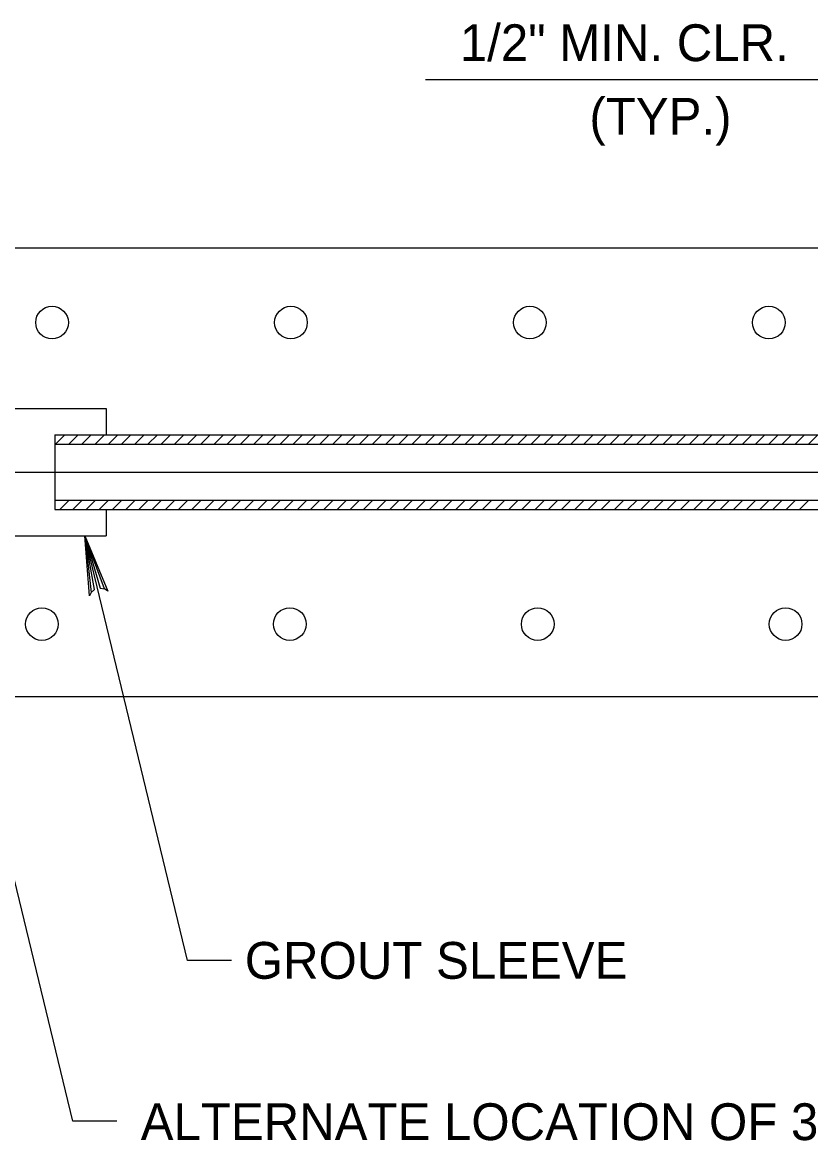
# Model space of a CAD drawing. Extents: x 641328 to 643024, y 298283 to 300065.
# Drawn here: x 642334.5 to 642398.8, y 299308 to 299399.2 of the extents above; entities that cross this region are included whole.
import ezdxf

# ---------------------------------------------------------------- set-up
doc = ezdxf.new("R2010")
doc.units = 0
doc.layers.add('2', color=7, linetype='Continuous')
doc.layers.add('Default', color=7, linetype='Continuous')

msp = doc.modelspace()

# ---------------------------------------------------------------- linework, layer by layer
at = {"layer": '2'}
for p, q in [((642367.417, 299394.518), (642420.173, 299394.518)), ((642292.048, 299380.803), (642421.968, 299380.803)), ((642331.817, 299367.696), (642341.364, 299367.696)), ((642341.364, 299367.696), (642341.364, 299365.563)), ((642337.162, 299365.563), (642423.111, 299365.563)), ((642337.162, 299365.563), (642337.162, 299359.467)), ((642337.229, 299364.801), (642337.991, 299365.563)), ((642338.307, 299364.801), (642339.069, 299365.563)), ((642339.385, 299364.801), (642340.147, 299365.563)), ((642340.462, 299364.801), (642341.224, 299365.563)), ((642341.54, 299364.801), (642342.302, 299365.563)), ((642342.618, 299364.801), (642343.38, 299365.563)), ((642343.695, 299364.801), (642344.457, 299365.563)), ((642344.773, 299364.801), (642345.535, 299365.563)), ((642345.85, 299364.801), (642346.612, 299365.563)), ((642346.928, 299364.801), (642347.69, 299365.563)), ((642348.006, 299364.801), (642348.768, 299365.563)), ((642349.083, 299364.801), (642349.845, 299365.563)), ((642350.161, 299364.801), (642350.923, 299365.563)), ((642351.239, 299364.801), (642352.001, 299365.563)), ((642352.316, 299364.801), (642353.078, 299365.563)), ((642353.394, 299364.801), (642354.156, 299365.563)), ((642354.472, 299364.801), (642355.234, 299365.563)), ((642355.549, 299364.801), (642356.311, 299365.563)), ((642356.627, 299364.801), (642357.389, 299365.563)), ((642357.704, 299364.801), (642358.466, 299365.563)), ((642358.782, 299364.801), (642359.544, 299365.563)), ((642359.86, 299364.801), (642360.622, 299365.563)), ((642360.937, 299364.801), (642361.699, 299365.563)), ((642362.015, 299364.801), (642362.777, 299365.563)), ((642363.093, 299364.801), (642363.855, 299365.563)), ((642364.17, 299364.801), (642364.932, 299365.563)), ((642365.248, 299364.801), (642366.01, 299365.563)), ((642366.325, 299364.801), (642367.087, 299365.563)), ((642367.403, 299364.801), (642368.165, 299365.563)), ((642368.481, 299364.801), (642369.243, 299365.563)), ((642369.558, 299364.801), (642370.32, 299365.563)), ((642370.636, 299364.801), (642371.398, 299365.563)), ((642371.714, 299364.801), (642372.476, 299365.563)), ((642372.791, 299364.801), (642373.553, 299365.563)), ((642373.869, 299364.801), (642374.631, 299365.563)), ((642374.947, 299364.801), (642375.709, 299365.563)), ((642376.024, 299364.801), (642376.786, 299365.563)), ((642377.102, 299364.801), (642377.864, 299365.563)), ((642378.179, 299364.801), (642378.941, 299365.563)), ((642379.257, 299364.801), (642380.019, 299365.563)), ((642380.335, 299364.801), (642381.097, 299365.563)), ((642381.412, 299364.801), (642382.174, 299365.563)), ((642382.49, 299364.801), (642383.252, 299365.563)), ((642383.568, 299364.801), (642384.33, 299365.563)), ((642384.645, 299364.801), (642385.407, 299365.563)), ((642385.723, 299364.801), (642386.485, 299365.563)), ((642386.801, 299364.801), (642387.563, 299365.563)), ((642387.878, 299364.801), (642388.64, 299365.563)), ((642388.956, 299364.801), (642389.718, 299365.563)), ((642390.033, 299364.801), (642390.795, 299365.563)), ((642391.111, 299364.801), (642391.873, 299365.563)), ((642392.189, 299364.801), (642392.951, 299365.563)), ((642393.266, 299364.801), (642394.028, 299365.563)), ((642394.344, 299364.801), (642395.106, 299365.563)), ((642395.422, 299364.801), (642396.184, 299365.563)), ((642396.499, 299364.801), (642397.261, 299365.563)), ((642397.577, 299364.801), (642398.339, 299365.563)), ((642398.654, 299364.801), (642399.416, 299365.563)), ((642337.162, 299364.801), (642423.111, 299364.801)), ((642229.139, 299362.515), (642534.829, 299362.515)), ((642337.162, 299360.229), (642423.111, 299360.229)), ((642337.567, 299359.467), (642338.329, 299360.229)), ((642338.644, 299359.467), (642339.406, 299360.229)), ((642339.722, 299359.467), (642340.484, 299360.229)), ((642340.8, 299359.467), (642341.562, 299360.229)), ((642341.877, 299359.467), (642342.639, 299360.229)), ((642342.955, 299359.467), (642343.717, 299360.229)), ((642344.033, 299359.467), (642344.795, 299360.229)), ((642345.11, 299359.467), (642345.872, 299360.229)), ((642346.188, 299359.467), (642346.95, 299360.229)), ((642347.265, 299359.467), (642348.027, 299360.229)), ((642348.343, 299359.467), (642349.105, 299360.229)), ((642349.421, 299359.467), (642350.183, 299360.229)), ((642350.498, 299359.467), (642351.26, 299360.229)), ((642351.576, 299359.467), (642352.338, 299360.229)), ((642352.654, 299359.467), (642353.416, 299360.229)), ((642353.731, 299359.467), (642354.493, 299360.229)), ((642354.809, 299359.467), (642355.571, 299360.229)), ((642355.887, 299359.467), (642356.649, 299360.229)), ((642356.964, 299359.467), (642357.726, 299360.229)), ((642358.042, 299359.467), (642358.804, 299360.229)), ((642359.119, 299359.467), (642359.881, 299360.229)), ((642360.197, 299359.467), (642360.959, 299360.229)), ((642361.275, 299359.467), (642362.037, 299360.229)), ((642362.352, 299359.467), (642363.114, 299360.229)), ((642363.43, 299359.467), (642364.192, 299360.229)), ((642364.508, 299359.467), (642365.27, 299360.229)), ((642365.585, 299359.467), (642366.347, 299360.229)), ((642366.663, 299359.467), (642367.425, 299360.229)), ((642367.74, 299359.467), (642368.502, 299360.229)), ((642368.818, 299359.467), (642369.58, 299360.229)), ((642369.896, 299359.467), (642370.658, 299360.229)), ((642370.973, 299359.467), (642371.735, 299360.229)), ((642372.051, 299359.467), (642372.813, 299360.229)), ((642373.129, 299359.467), (642373.891, 299360.229)), ((642374.206, 299359.467), (642374.968, 299360.229)), ((642375.284, 299359.467), (642376.046, 299360.229)), ((642376.362, 299359.467), (642377.124, 299360.229)), ((642377.439, 299359.467), (642378.201, 299360.229)), ((642378.517, 299359.467), (642379.279, 299360.229)), ((642379.594, 299359.467), (642380.356, 299360.229)), ((642380.672, 299359.467), (642381.434, 299360.229)), ((642381.75, 299359.467), (642382.512, 299360.229)), ((642382.827, 299359.467), (642383.589, 299360.229)), ((642383.905, 299359.467), (642384.667, 299360.229)), ((642384.983, 299359.467), (642385.745, 299360.229)), ((642386.06, 299359.467), (642386.822, 299360.229)), ((642387.138, 299359.467), (642387.9, 299360.229)), ((642388.216, 299359.467), (642388.978, 299360.229)), ((642389.293, 299359.467), (642390.055, 299360.229)), ((642390.371, 299359.467), (642391.133, 299360.229)), ((642391.448, 299359.467), (642392.21, 299360.229)), ((642392.526, 299359.467), (642393.288, 299360.229)), ((642393.604, 299359.467), (642394.366, 299360.229)), ((642394.681, 299359.467), (642395.443, 299360.229)), ((642395.759, 299359.467), (642396.521, 299360.229)), ((642396.837, 299359.467), (642397.599, 299360.229)), ((642397.914, 299359.467), (642398.676, 299360.229)), ((642337.162, 299359.467), (642423.111, 299359.467)), ((642341.364, 299359.467), (642341.364, 299357.334)), ((642321.325, 299357.334), (642341.364, 299357.334)), ((642347.987, 299322.722), (642339.609, 299357.334)), ((642292.048, 299344.227), (642423.111, 299344.227)), ((642338.628, 299309.615), (642330.25, 299344.227))]:
    msp.add_line(p, q, dxfattribs=at)
msp.add_lwpolyline([(642340.132, 299352.714), (642340.416, 299352.96), (642339.609, 299357.334), (642340.132, 299352.714), (642339.991, 299352.437), (642339.609, 299357.334), (642340.867, 299353.073), (642341.226, 299352.993), (642339.609, 299357.334), (642341.499, 299352.802), (642341.226, 299352.993)], dxfattribs=at)
for centre in [(642336.942, 299374.707), (642356.436, 299374.707), (642375.931, 299374.707), (642395.425, 299374.707), (642336.117, 299350.132), (642356.341, 299350.132), (642376.566, 299350.132), (642396.791, 299350.132)]:
    msp.add_circle(centre, 1.333, dxfattribs=at)
at = {"layer": 'Default'}
for p, q in [((642351.589, 299322.722), (642347.987, 299322.722)), ((642342.23, 299309.615), (642338.628, 299309.615))]:
    msp.add_line(p, q, dxfattribs=at)

# ---------------------------------------------------------------- texts
at = {"layer": '2'}
for s, height, p in [('1/2" MIN. CLR.', 2.99999, (642370.214, 299396.018)), ('(TYP.)', 3, (642380.786, 299390.018)), ('GROUT SLEEVE', 3, (642352.671, 299321.222)), ('ALTERNATE LOCATION OF 3/4" I.D.', 3, (642344.177, 299308.071))]:
    msp.add_text(s, height=height, dxfattribs=at).set_placement(p)

doc.saveas('drawing.dxf')
